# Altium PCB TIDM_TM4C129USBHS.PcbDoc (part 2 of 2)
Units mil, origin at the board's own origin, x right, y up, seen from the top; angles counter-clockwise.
Board outline 3900 x 3450 mil, 4 copper layers (Component Side, Ground Plane, Power Plane, Solder Side), stack 59.6 mil thick; 136 components, 129 nets, 585 pads, 295 vias.
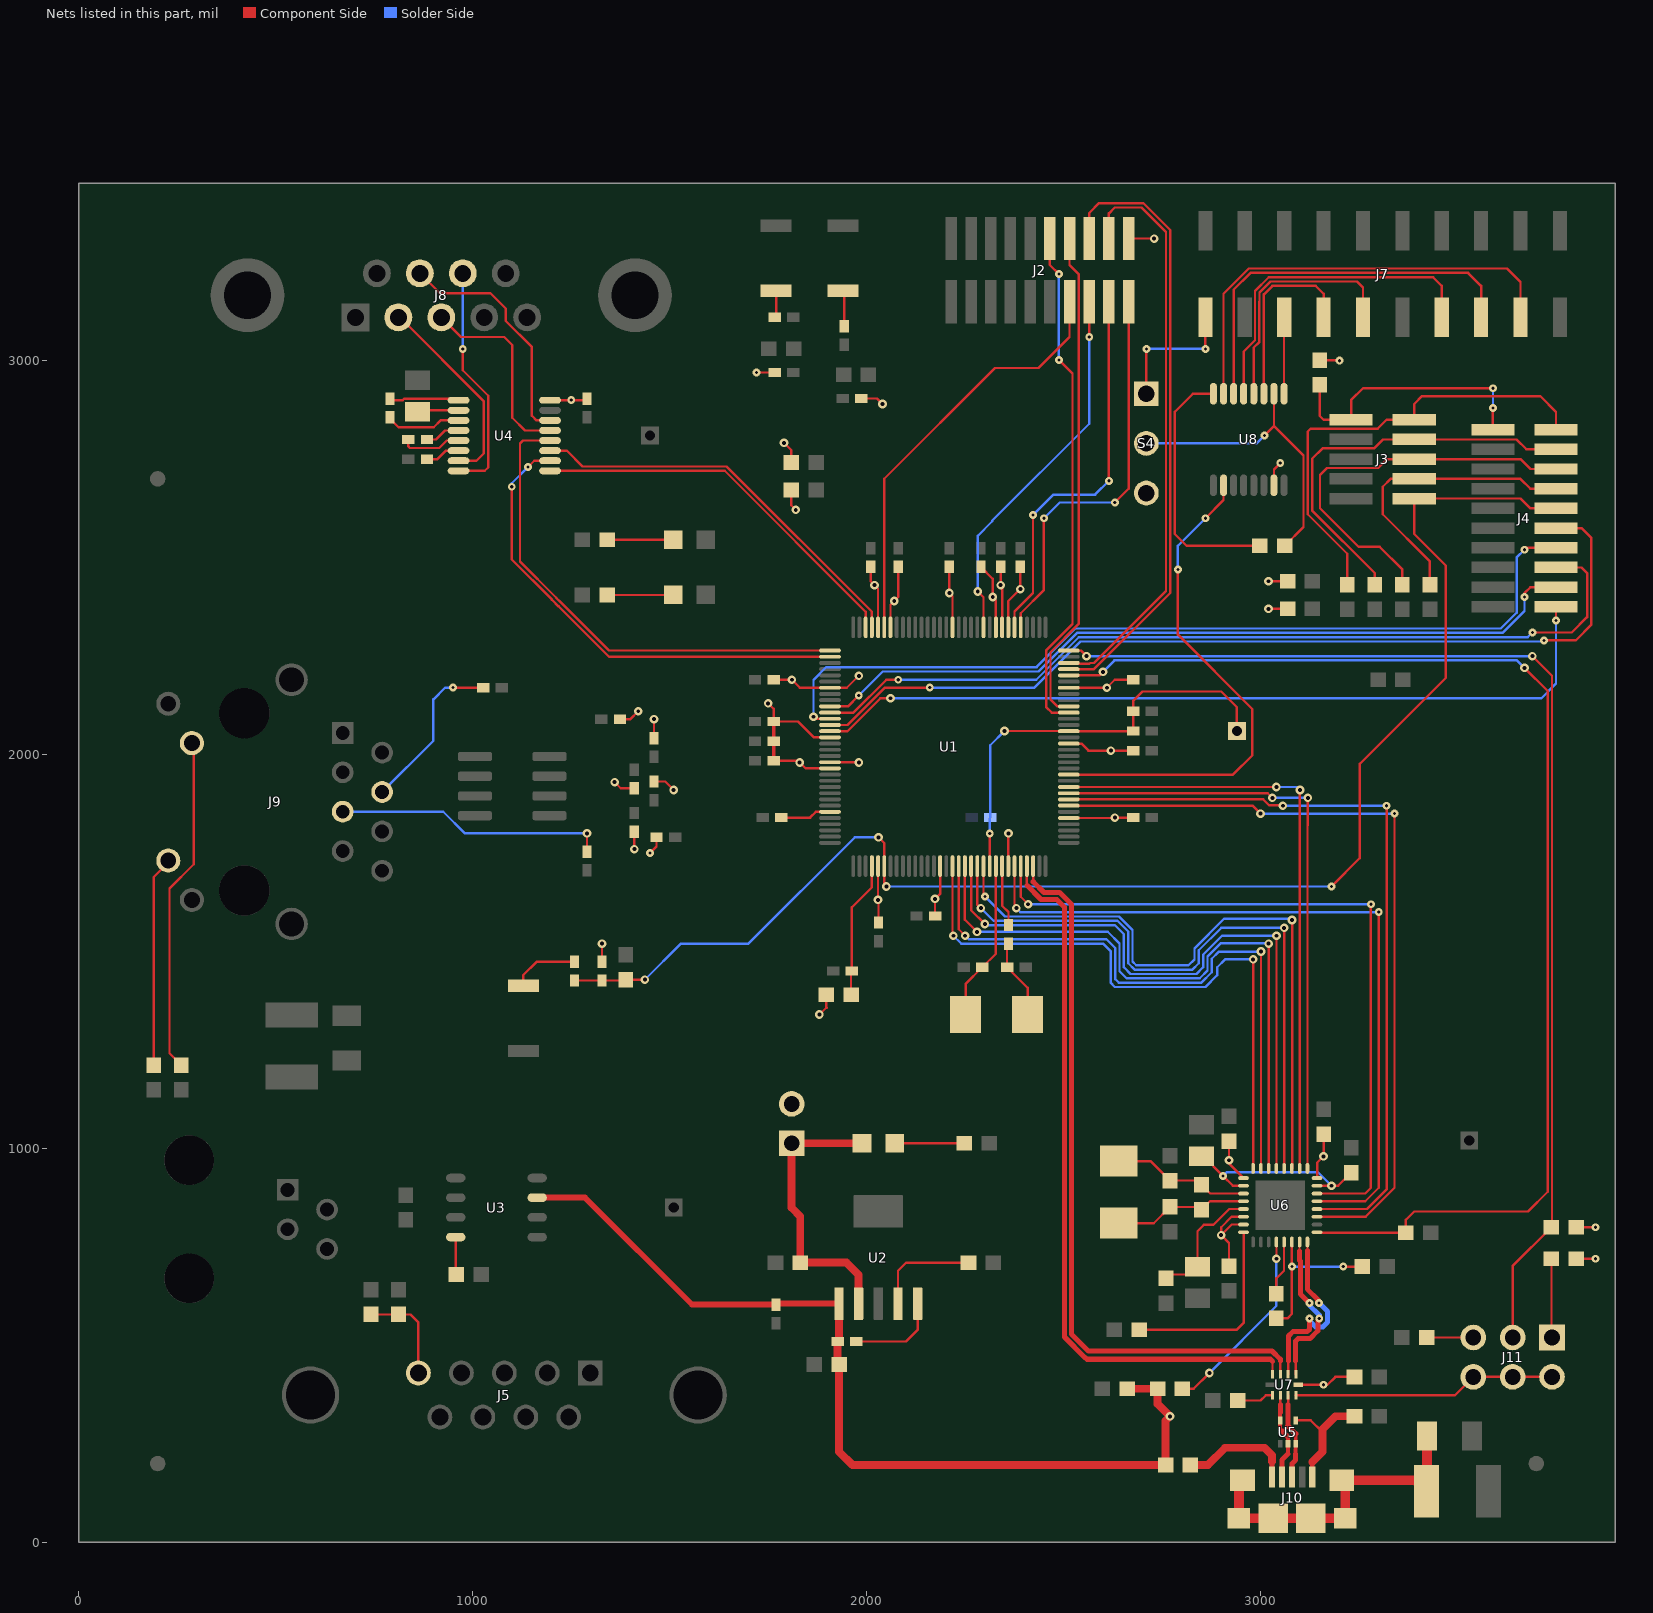
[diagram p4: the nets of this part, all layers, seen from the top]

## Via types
v1: diameter 22, hole 10, Component Side to Solder Side, 140 vias
v2: diameter 20, hole 8, Component Side to Solder Side, 139 vias
v3: diameter 19.68, hole 8, Component Side to Solder Side, 16 vias

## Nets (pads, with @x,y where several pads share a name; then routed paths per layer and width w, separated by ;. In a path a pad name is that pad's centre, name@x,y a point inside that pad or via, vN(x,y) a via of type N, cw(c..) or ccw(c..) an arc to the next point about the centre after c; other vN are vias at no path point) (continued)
MCU_GPIO5: U1.108 U8.10 | length 1298.3
  Component Side w6: U1.108@2513.15,1949.13 2930.19,1949.13 2979,1997.94 2979,2115.44 2790,2304.44 v2(2790,2470) ; v2(2860,2600) 2906.02,2646.02 U8.10@2906.02,2683.86
  Solder Side w6: v2(2790,2470) 2790,2530 v2(2860,2600)
NetC1_1: C1.1 R1.2 U1.68 | length 348.3
  Component Side w6: R1.2@1960.28,1390.5 1960.28,1448.37 C1.1@1962.4,1450.5 1962.4,1612.4 2013.15,1663.15 U1.68@2013.15,1716.85
NetC17_1: C17.1 C18.1 C19.1 TP1.1 U1.87 U1.115 | length 1112.4
  Component Side w4.8: C18.1@2662.99,2059.37 2662.99,2060 C18.1@2676.38,2060
  Component Side w6: U1.87@2312.36,1716.85 v2(2312.36,1800) ; v1(2350,2060) 2512.52,2060 U1.115@2513.15,2059.37 C18.1@2662.99,2059.37 ; C18.1@2676.38,2060 C17.1@2676.38,2110 2676.38,2136.38 2700,2160 2900,2160 2940,2120 TP1.1@2940,2060
  Solder Side w6: v2(2312.36,1800) 2312.36,1838.74 C19.1@2313.62,1840 2313.62,2023.62 v1(2350,2060)
NetC20_1: C20.1 U1.88 Y1.2 | length 408.7
  Component Side w6: Y1.2@2251.26,1340 2251.26,1417.64 C20.1@2293.62,1460 2328.11,1494.49 U1.88@2328.11,1716.85
NetC21_1: C21.1 R2.2 Y1.1 | length 203.2
  Component Side w6: R2.2@2360,1520 2356.38,1516.38 C21.1@2356.38,1460 2360,1456.38 2408.74,1407.64 Y1.1@2408.74,1340
NetC24_1: C24.1 U2.4 | length 271.8
  Component Side w6: U2.4@2080,605.44 U2.4@2079.49,605.95 2079.49,689.49 2100,710 C24.1@2258.5,710
NetC25_1: C25.1 D1.1 J1.1 U2.2 | length 725
  Component Side w20: U2.2@1979.49,605.95 1979.49,679.49 1948.98,710 C25.1@1831.5,710 1831.5,827.49 1809.49,849.49 J1.1@1809.49,1013.08 D1.1@1988.15,1013.08
NetC27_1: C27.1 J5.5 R20.2 | length 257.1
  Component Side w6: C27.1@741.46,578.5 R20.2@811.46,578.5 841.5,578.5 861.89,558.11 J5.5@861.89,429.92
NetC30_1: C30.1 U4.1 | length 180.4
  Component Side w6: C30.1@790,2903.62 794.06,2899.57 821.75,2899.57 825.19,2903 963.86,2903 U4.1@963.86,2899.57
NetC30_2: C30.2 U4.3 | length 196.3
  Component Side w6: C30.2@790,2856.38 790,2852.44 811.65,2830.79 900.79,2830.79 918.39,2848.39 U4.3@963.86,2848.39 U4.3@965.47,2850
NetC31_1: C31.1 U4.4 | length 90.8
  Component Side w6: C31.1@883.62,2800 906.46,2800 929.25,2822.8 U4.4@963.86,2822.8 U4.4@963.03,2823.62
NetC31_2: C31.2 U4.5 | length 154.8
  Component Side w6: C31.2@836.38,2800 836.38,2781.97 840,2778.35 914.8,2778.35 933.66,2797.2 U4.5@963.86,2797.2
NetC32_2: C32.2 U4.2 | length 105.5
  Component Side w6: C32.2@860,2870 863.98,2873.98 U4.2@963.86,2873.98
NetC33_1: C33.1 U4.6 | length 89.2
  Component Side w6: C33.1@883.62,2750 910,2750 931.61,2771.61 U4.6@963.86,2771.61
NetC48_1: C48.1 R36.2 U6.28 Y2.1 | length 345.6
  Component Side w6: Y2.1@2640,810.26 2728.76,810.26 C48.1@2770,851.5 2843.35,851.5 R36.2@2850.2,844.65 2871.54,865.98 U6.28@2956.89,865.98
NetC49_1: C49.1 R36.1 U6.27 Y2.2 | length 350.9
  Component Side w6: Y2.2@2640,967.74 2720.76,967.74 C49.1@2770,918.5 2839.33,918.5 R36.1@2850.2,907.64 2872.17,885.67 U6.27@2956.89,885.67
NetD1_2: D1.2 R7.1 | length 177.2
  Component Side w6: D1.2@2070.83,1013.08 R7.1@2248,1013.08
NetD2_2: D2.2 R21.1 | length 167.2
  Component Side w6: R21.1@1341.32,2545.28 D2.2@1508.49,2545.28
NetD3_2: D3.2 R22.1 | length 167.2
  Component Side w6: R22.1@1341.32,2405.28 D3.2@1508.49,2405.28
NetJ7_1: J7.1 S4.1 | length 344
  Component Side w6: S4.1@2710,2916 v2(2710,3030) ; v2(2860,3030) J7.1@2860,3110
  Solder Side w6: v2(2710,3030) v2(2860,3030)
NetJ7_5: J7.5 U8.1 | length 194
  Component Side w6: U8.1@3059.57,2916.14 3059.57,3109.57 J7.5@3060,3110
NetJ7_7: J7.7 U8.3 | length 481.1
  Component Side w6: U8.3@3008.39,2916.14 3008.39,3168.39 3030,3190 3140,3190 3160,3170 J7.7@3160,3110
NetJ7_9: J7.9 U8.4 | length 619
  Component Side w6: U8.4@2982.8,2916.14 2982.8,3033.24 2997,3047.44 2997,3150 2997.39,3150.39 2997.39,3172.94 3025.44,3201 3244.5,3201 3260,3185.5 J7.9@3260,3110
NetJ7_13: J7.13 U8.5 | length 850.5
  Component Side w6: U8.5@2957.2,2916.14 2957.2,3023.2 2986,3052 2986,3177.11 3020.89,3212 3438,3212 3460,3190 J7.13@3460,3110
NetJ7_15: J7.15 U8.6 | length 1003.7
  Component Side w6: U8.6@2931.61,2916.14 2931.61,3180 2974.61,3223 3527,3223 3560,3190 J7.15@3560,3110
NetJ7_17: J7.17 U8.7 | length 1138.4
  Component Side w6: U8.7@2906.02,2916.14 2906.02,3169.97 2970.06,3234 3626,3234 3660,3200 J7.17@3660,3110
NetJ8_2: J8.2 U4.7 | length 509.6
  Component Side w6: J8.2@810.94,3110.08 814.92,3110.08 1028.22,2896.78 1028.22,2765 1009.24,2746.02 U4.7@963.86,2746.02
NetJ8_3: J8.3 U4.13 | length 503.5
  Component Side w6: J8.3@920,3110.08 970.08,3060 1080,3060 1100,3040 1100,2855 1132.2,2822.8 U4.13@1196.14,2822.8
NetJ8_7: J8.7 U4.14 | length 606.1
  Component Side w6: J8.7@865.47,3221.89 916.36,3171 1045.11,3171 1083.49,3132.63 1083.49,3101.07 1150,3034.56 1150,2860 1161.61,2848.39 U4.14@1196.14,2848.39
NetJ8_8: J8.8 U4.8 | length 598.5
  Component Side w6: U4.8@963.86,2720.43 1030.43,2720.43 1039.22,2729.22 1039.22,2911.02 974.53,2975.71 v2(974.53,3030)
  Solder Side w6: v2(974.53,3030) J8.8@974.53,3221.89
NetJ9_10: J9.10 R32.1 | length 855.5
  Component Side w6: R32.1@260,1211.5 230,1241.5 230,1660 291.73,1721.73 J9.10@291.73,2029.02
NetJ9_11: J9.11 R33.1 | length 536.8
  Component Side w6: R33.1@190,1211.5 190,1689.09 J9.11@231.89,1730.98
NetJ11_1: J11.1 R41.1 | length 200.6
  Component Side w6: R41.1@3738.5,720 3738.5,521.5 J11.1@3740,520
NetJ11_2: J11.2 J11.4 J11.6 U7.9 | length 669.8
  Component Side w6: U7.9@3089.53,373.43 3493.43,373.43 J11.6@3540,420 J11.4@3640,420 J11.2@3740,420
NetJ11_5: J11.5 R42.1 | length 120.6
  Component Side w6: R42.1@3421.5,520 J11.5@3540,520 J11.5@3541.5,521.5
NetR2_1: R2.1 U1.89 | length 156.3
  Component Side w6: U1.89@2343.86,1716.85 2343.86,1616.14 2360,1600 R2.1@2360,1567.24
NetR3_2: R3.2 U1.59 | length 129.3
  Component Side w6: R3.2@1783.62,1840 1856.35,1840 1871,1854.65 U1.59@1906.85,1854.65
NetR4_2: R4.2 S1.2 | length 171.2
  Component Side w6: S1.2@1128.19,1412.68 1128.19,1440 1161.81,1473.62 R4.2@1258.19,1473.62
NetR6_2: R6.2 U2.5 | length 235
  Component Side w6: R6.2@1973.62,510 2100,510 2130,540 2129.49,540.51 U2.5@2129.49,605.95
NetR18_2: R18.2 U3.8 | length 95.8
  Component Side w6: U3.8@956.65,775 956.65,681.85 R18.2@958.5,680
NetR23_2: R23.2 S2.2 | length 83.7
  Component Side w6: R23.2@1943,3087.61 S2.2@1943,3171.31
NetR25_2: R25.2 S3.2 | length 68.8
  Component Side w6: R25.2@1766.38,3110 1770,3113.62 S3.2@1770,3177.32
NetR27_1: R27.1 U8.8 | length 656.5
  Component Side w6: U8.8@2880.43,2916.14 2828.14,2916.14 2782,2870 2782,2560 2812,2530 R27.1@2998.5,2530
NetR27_2: R27.2 S4.2 U8.2 | length 779.1
  Component Side w6: v2(3010,2810) 3033.98,2833.98 ; U8.2@3033.98,2916.14 3033.98,2833.98 ; R27.2@3061.5,2530 3109,2577.5 3109,2758.95 3033.98,2833.98
  Solder Side w6: S4.2@2710,2790 2990,2790 v2(3010,2810)
NetR35_1: R35.1 U6.5 | length 139.6
  Component Side w6: R35.1@3040,631.5 3040,670 3059.5,689.5 3059.5,762.29 U6.5@3060.04,762.83
NetR37_1: R37.1 U6.4 | length 488.5
  Component Side w6: R37.1@2801.5,390 2830,390 v1(2870,430) ; v1(3040,720) 3040.36,720.36 U6.4@3040.36,762.83
  Solder Side w6: v1(2870,430) 3040,600 v1(3040,720)
NetR38_2: R38.2 U6.32 | length 502.7
  Component Side w6: R38.2@2691.5,540 2940,540 2956.89,556.89 U6.32@2956.89,787.24
NetR40_2: R40.2 U7.6 | length 95.2
  Component Side w6: R40.2@2941.5,360 3000,360 3013.43,373.43 U7.6@3030.47,373.43 U7.6@3030,372.95
RST_N: C22.1 J3.10 J4.10 R4.1 R5.1 U1.70 | length 3694.3
  Component Side w6: R4.1@1258.19,1426.38 R5.1@1328.19,1426.38 1386.06,1426.38 C22.1@1388.19,1428.5 v1(1436.69,1428.5) ; v1(2030,1790) 2044.65,1775.35 U1.70@2044.65,1716.85 2044.65,1670.35 v1(2050,1665) ; v2(3180,1665) 3252,1737 3252,1976.44 3470,2194.44 3470,2480 3390.12,2559.88 J3.10@3390.12,2650 3660,2650 3685,2625 J4.10@3750.12,2625
  Solder Side w6: v1(1436.69,1428.5) 1528.19,1520 1700,1520 1970,1790 v1(2030,1790) ; v1(2050,1665) v2(3180,1665)
SSI3CLK: J2.2 U1.5 | length 1022.2
  Component Side w6: U1.5@2391.1,2323.15 2391.1,2359 2450,2417.9 v2(2450,2600) ; v2(2630,2640) 2665,2675 J2.2@2665,3149.88
  Solder Side w6: v2(2450,2600) 2490,2640 v2(2630,2640)
SSI3FSS: J2.4 U1.6 | length 988.1
  Component Side w6: U1.6@2375.35,2323.15 2375.35,2363 2422.35,2410 v2(2422.35,2608.35) ; v2(2615,2695) J2.4@2615,3149.88
  Solder Side w6: v2(2422.35,2608.35) 2474,2660 2580,2660 v2(2615,2695)
SSI3XDAT0: J2.6 U1.11 | length 962.6
  Component Side w6: v1(2282,2414) 2296.61,2399.39 U1.11@2296.61,2323.15 ; v2(2565,3060) J2.6@2565,3149.88 J2.6@2565,3162.5
  Solder Side w6: v1(2282,2414) 2282,2555.13 2319,2592.13 2319,2594 2565,2840 v2(2565,3060)
SSI3XDAT1: J2.8 U1.27 | length 1086.3
  Component Side w6: U1.27@2044.65,2323.15 2044.65,2700.17 2325.97,2981.5 2436.5,2981.5 2515,3060 J2.8@2515,3149.88
SSI3XDAT2: J2.9 U1.118 | length 1304.2
  Component Side w6: J2.9@2465,3310.12 2465,3243 v2(2488,3220) ; v2(2488,3002) 2522.59,2967.41 2522.59,2331.55 2455.59,2264.56 2455.59,2121.02 2470,2106.61 U1.118@2513.15,2106.61
  Solder Side w6: v2(2488,3002) v2(2488,3220)
SSI3XDAT3: J2.7 U1.119 | length 1263.1
  Component Side w6: U1.119@2513.15,2122.36 2484.23,2122.36 2466.59,2140 2466.59,2260 2538,2331.41 2538,3220 2515,3243 J2.7@2515,3310.12
TCK_INT: J3.4 J4.4 R12.1 | length 1035.1
  Component Side w6: R12.1@3290,2431.49 3290,2460.75 3131,2619.75 3131,2751 3157.43,2777.43 3288.11,2777.43 3310.68,2800 J3.4@3390.12,2800 3650,2800 3675,2775 J4.4@3750.12,2775
TDI_INT: J3.8 J4.8 R14.1 | length 757
  Component Side w6: R14.1@3430,2431.49 3430,2490 3310,2610 3310,2680 3330,2700 J3.8@3390.12,2700 3660,2700 3685,2675 J4.8@3750.12,2675
TDO_INT: J3.6 J4.6 R13.1 | length 1022.6
  Component Side w6: R13.1@3360,2431.49 3360,2470 3302.22,2527.78 3248.55,2527.78 3151,2625.33 3151,2710 3168.43,2727.43 3298.43,2727.43 3321,2750 J3.6@3390.12,2750 3660,2750 3685,2725 J4.6@3750.12,2725
TMS_INT: J3.2 J4.2 R11.1 | length 1182.3
  Component Side w6: R11.1@3220,2431.49 3220,2510 3120,2610 3120,2820 3127.43,2827.43 3297.43,2827.43 3320,2850 3390,2850 J3.2@3390.12,2850 3390.12,2890 3410.12,2910 3710.12,2910 3750.12,2870 J4.2@3750.12,2825
TRCLK: J4.12 U1.45 | length 2360
  Component Side w6: U1.45@1906.85,2075.12 1951.26,2075.12 2046.14,2170 v2(2160,2170) ; v2(3720,2290) 3800,2290 3840,2330 3840,2550 3815,2575 J4.12@3750.12,2575
  Solder Side w6: v2(2160,2170) 2426.06,2170 2543.06,2287 3717,2287 v2(3720,2290) ; 2525.82,2268.23 2526.59,2269
TRD0: J4.14 U1.44 | length 2243.6
  Component Side w6: v1(1865,2096) 1870.13,2090.87 U1.44@1906.85,2090.87 ; v2(3670,2520) 3675,2525 J4.14@3750.12,2525
  Solder Side w6: v1(1865,2096) 1865,2189.5 1897.5,2222 2431.39,2222 2529.39,2320 3610,2320 3650,2360 3650,2500 v2(3670,2520)
TRD1: J4.16 U1.43 | length 2219.2
  Component Side w6: U1.43@1906.85,2106.61 1966.61,2106.61 2050,2190 v2(2080,2190) ; v2(3690,2310) 3790,2310 3829,2349 3829,2461 3815,2475 J4.16@3750.12,2475
  Solder Side w6: v2(2080,2190) 2430.5,2190 2538.5,2298 3678,2298 v2(3690,2310)
TRD2: J4.18 U1.42 | length 1995.3
  Component Side w6: U1.42@1906.85,2122.36 1952.36,2122.36 v2(1980,2150) ; v2(3670,2400) 3670,2410 3685,2425 J4.18@3750.12,2425
  Solder Side w6: v2(1980,2150) 2041,2211 2435.94,2211 2533.94,2309 3614.56,2309 3670,2364.44 v2(3670,2400)
TRD3: J4.20 U1.46 | length 2088.2
  Component Side w6: U1.46@1906.85,2059.37 1951.07,2059.37 2034.7,2143 v1(2060.5,2143) ; v2(3750.12,2340.12) J4.20@3750.12,2375
  Solder Side w6: v1(2060.5,2143) 3713,2143 3750.12,2180.12 v2(3750.12,2340.12)
U0CTS: U1.30 U4.9 | length 988.9
  Component Side w6: U4.9@1196.14,2720.43 1639.57,2720.43 1997.4,2362.6 U1.30@1997.4,2323.15
U0RTS: U1.29 U4.11 | length 1025.8
  Component Side w6: U4.11@1196.14,2771.61 1238.39,2771.61 1278.57,2731.43 1644.12,2731.43 2013.15,2362.41 U1.29@2013.15,2323.15
U0RX: U1.33 U4.12 | length 1264.9
  Component Side w6: U4.12@1196.14,2797.2 1127.2,2797.2 1120,2790 1120,2490 1211.83,2398.17 1211.83,2397.83 1222.37,2387.28 1222.72,2387.28 1345.91,2264.09 U1.33@1906.85,2264.09 U1.33@1912,2264.09
U0TX: U1.34 U4.10 | length 1224.7
  Component Side w6: v2(1099,2680) 1099,2495.44 1200.83,2393.61 1200.83,2393.27 1217.82,2376.28 1218.16,2376.28 1346.1,2248.35 U1.34@1906.85,2248.35 ; v2(1140,2730) 1156.02,2746.02 U4.10@1196.14,2746.02
  Solder Side w6: v2(1099,2680) 1099,2689 v2(1140,2730)
U2RX: J2.5 U1.125 | length 1568.3
  Component Side w6: U1.125@2513.15,2216.85 2576.85,2216.85 2771,2411 2771,3331.28 2702.28,3400 2590,3400 2565,3375 J2.5@2565,3310.12
U2TX: J2.3 U1.126 | length 1476
  Component Side w6: U1.126@2513.15,2232.6 2514.75,2231 2565.87,2231 2567.47,2232.6 2577.04,2232.6 2760,2415.56 2760,3326.72 2697.72,3389 2630,3389 2615,3374 J2.3@2615,3310.12
U_GND: FB2.1 J10.5 U5.4 | length 307
  Component Side w6: U5.4@3089.21,309.53 3127.46,309.53 3156.99,280
  Component Side w12: J10.5@3131.18,166.34 3131.18,204.19
  Component Side w20: 3131.18,204.19 3156.99,230 3156.99,260 ; 3156.67,260.31 3156.99,260 ; FB2.1@3238.5,320 3190,320 3156.99,286.99 3156.99,280 3156.99,260
U_SHIELD: C52.1 J10.6 J10.7 J10.8 J10.9 J10.10 J10.11 R44.2 | length 827.8
  Component Side w25: J10.6@2954.02,158.02 2945.16,149.16 J10.8@2945.16,61.02 J10.10@3127.24,61.02 J10.11@3214.84,61.02 3214.84,148.62 J10.7@3205.98,157.48 3393.78,157.48 C52.1@3421.26,130 3422.91,131.65 R44.2@3422.91,260
U_VBUS: FB1.2 J10.1 | length 287.9
  Component Side w12: J10.1@3028.82,166.34 3028.82,205
  Component Side w20: FB1.2@2821.69,196.14 2866.14,196.14 2910,240 3010,240 3028.82,221.18 3028.82,205
ULPI_CLK: U1.92 U6.14 | length 1837.1
  Component Side w6: U1.92@2391.1,1716.85 2391.1,1638.9 v1(2410,1620) ; U6.14@3143.51,885.67 3265.67,885.67 3280,900 v2(3280,1620)
  Solder Side w6: v1(2410,1620) v2(3280,1620)
ULPI_D0: U1.81 U6.24 | length 1611
  Component Side w6: U1.81@2217.87,1716.85 2217.87,1542.13 v1(2220,1540) ; U6.24@2981.3,949.45 v1(2981.3,1480)
  Solder Side w6: v1(2220,1540) 2240,1520 2600,1520 2620,1500 2620,1420 2630,1410 2860,1410 2890,1440 2890,1460 2910,1480 v1(2981.3,1480)
ULPI_D1: U1.82 U6.23 | length 1633.7
  Component Side w6: U1.82@2233.62,1716.85 2233.62,1556.38 v1(2250,1540) ; U6.23@3000.99,949.45 v1(3000.99,1500)
  Solder Side w6: v1(2250,1540) 2259,1531 2609,1531 2631,1509 2631,1430 2640,1421 2850,1421 2876.22,1447.22 2876.22,1481.78 2893.44,1499 2999.99,1499 v1(3000.99,1500)
ULPI_D2: U1.83 U6.22 | length 1638.3
  Component Side w6: U1.83@2249.37,1716.85 2249.37,1580.63 v1(2280,1550) ; U6.22@3020.67,949.45 v1(3020.67,1520)
  Solder Side w6: v1(2280,1550) 2612,1550 2642,1520 2642,1450 2660,1432 2845.44,1432 2865.22,1451.78 2865.22,1487.22 2898.56,1520.56 3020.11,1520.56 v1(3020.67,1520)
ULPI_D3: U1.84 U6.21 | length 1652.8
  Component Side w6: U1.84@2265.12,1716.85 2265.12,1604.88 v1(2300,1570) ; U6.21@3040.36,949.45 v1(3040.36,1540)
  Solder Side w6: v1(2300,1570) 2303,1567 2630,1567 2653,1544 2653,1460 2670,1443 2837.22,1443 2854.22,1460 2854.22,1491.78 2902.44,1540 v1(3040.36,1540)
ULPI_D4: U1.85 U6.20 | length 1666.3
  Component Side w6: U1.85@2280.87,1716.85 2280.87,1619.13 v1(2290,1610) ; U6.20@3060.04,949.45 v1(3060.04,1560)
  Solder Side w6: v1(2290,1610) 2322,1578 2636.44,1578 2664,1550.44 2664,1470 2680,1454 2827.22,1454 2843.22,1470 2843.22,1503.22 2900,1560 v1(3060.04,1560)
ULPI_D5: U1.86 U6.19 | length 1674.9
  Component Side w6: U1.86@2296.61,1716.85 2296.61,1643.39 v2(2300,1640) ; U6.19@3079.73,949.45 3080,949.72 v1(3080,1580)
  Solder Side w6: v2(2300,1640) 2351,1589 2641,1589 2675,1555 2675,1474.56 2684.56,1465 2817.22,1465 2832.22,1480 2832.22,1507.78 2907.44,1583 3077,1583 v1(3080,1580)
ULPI_D6: U1.106 U6.18 | length 1550.8
  Component Side w6: U1.106@2513.15,1917.64 v1(3040,1917.64) ; U6.18@3099.41,949.45 3099.41,1909.41 v1(3100,1910)
  Solder Side w6: v1(3040,1917.64) 3092.36,1917.64 v1(3100,1910)
ULPI_D7: U1.105 U6.17 | length 1552.7
  Component Side w6: U1.105@2513.15,1901.89 3018.11,1901.89 v1(3030,1890) ; U6.17@3119.1,949.45 3119.1,1820 3120,1820.9 v1(3120,1890)
  Solder Side w6: v1(3030,1890) v1(3120,1890)
ULPI_DIR: U1.104 U6.12 | length 1984.8
  Component Side w6: U1.104@2513.15,1886.14 3006.99,1886.14 3022.13,1871 3055.46,1871 v1(3056.46,1870) ; U6.12@3143.31,846.16 3270,846.16 3320,896.16 v2(3320,1870)
  Solder Side w6: v1(3056.46,1870) v2(3320,1870)
ULPI_NXT: U1.103 U6.11 | length 2012.2
  Component Side w6: U1.103@2513.15,1870.39 2979.61,1870.39 v1(3000,1850) ; U6.11@3143.51,826.61 3266.61,826.61 3340,900 v2(3340,1850)
  Solder Side w6: v1(3000,1850) v2(3340,1850)
ULPI_STP: U1.91 U6.13 | length 1903.5
  Component Side w6: U1.91@2375.35,1716.85 2375.35,1614.65 v1(2380,1610) ; U6.13@3143.51,865.98 3265.98,865.98 3300,900 v2(3300,1600)
  Solder Side w6: v1(2380,1610) 2390,1600 v2(3300,1600)
USBCONN_N: J10.2 U5.2 U5.5 U7.7 | length 244.9
  Component Side w6: 3050.16,350 U7.7@3050.16,373.43 3050.16,350
  Component Side w9.45: U5.2@3069.53,250.47 3069.53,267.65
  Component Side w10: 3049.84,329.61 U5.5@3049.84,309.53 3049.84,287.33 3055.75,281.43 ; 3069.53,224.56 U5.2@3069.53,250.47
  Component Side w12.8: 3050.16,329.61 3050.16,350 ; J10.2@3054.41,166.34 3054.41,209.44 3069.53,224.56
  Component Side w14: 3055.75,281.43 3069.53,267.65
USBCONN_P: J10.3 U5.3 U7.8 | length 218.7
  Component Side w6: 3069.84,350.31 U7.8@3069.84,373.43
  Component Side w9.45: 3089.21,235.63 U5.3@3089.21,250.47 3089.21,275.52
  Component Side w10: 3089.21,224.56 3089.21,235.63
  Component Side w12.8: 3069.53,295.2 3069.53,350 ; J10.3@3080,166.34 3080,199.73 3089.21,208.94 3089.21,224.56
  Component Side w14: 3069.53,295.2 3089.21,275.52
USBD_N: U1.93 U7.4 | length 1845.3
  Component Side w6: 2406.85,1667.98 U1.93@2406.85,1716.85 ; U7.4@3030.47,426.57 3030.47,459.53
  Component Side w12.8: 2406.85,1667.98 2442.63,1632.2 2482.63,1632.2 2502.37,1612.45 2502.37,521.1 2555.27,468.2 2556.54,468.2 2559.96,464.79 3025.21,464.79 3030.47,459.53
USBD_P: U1.94 U7.3 | length 1846.9
  Component Side w6: U1.94@2422.6,1716.85 2422.85,1716.6 2422.85,1677.15 ; U7.3@3050.16,426.57 3050.16,460
  Component Side w12.8: 2422.85,1677.15 2450,1650 2490,1650 2520.17,1619.83 2520.17,528.47 2562.64,486 3029.17,486 3050.16,465.02 3050.16,460
USBHS_N: U6.8 U7.2 | length 473.7
  Component Side w5: 3118.9,741.1 U6.8@3118.9,762.69
  Component Side w6: U7.2@3069.84,426.57 3069.84,459.84 3070.79,460.79
  Component Side w12.8: 3070.79,460.79 3070.79,523.79 3081.79,534.79 3118.21,534.79 3124,540.59 v2(3124,568) ; 3118.73,700.17 3118.73,642.76 3145.21,616.28 3145.21,611.01 v2(3148.81,607.41) ; 3118.9,700.17 3118.9,741.1
  Solder Side w12.8: v2(3124,568) 3124,562.74 3140.14,546.6 3157.86,546.6 3170.4,559.14 3170.4,585.83 v2(3148.81,607.41)
USBHS_P: U6.7 U7.1 | length 426.7
  Component Side w5: 3099.21,739.21 U6.7@3099.21,762.69
  Component Side w6: 3088.59,460.47 3089.53,459.53 U7.1@3089.53,426.57 3089.53,453.21
  Component Side w12.8: 3088.59,460.47 3088.59,510.58 3095,516.99 3125.58,516.99 3145.4,536.81 3145.4,564.4 v2(3149,568) ; 3099.21,739.21 3099.21,715.61 3100.93,713.9 3100.93,630.3 v2(3123.81,607.41)
  Solder Side w12.8: v2(3123.81,607.41) 3123.81,602.15 3149,576.96 v2(3149,568)
USBMUX_SEL: J11.3 R43.1 U1.128 | length 2974.8
  Component Side w6: U1.128@2513.15,2264.09 2543.91,2264.09 v1(2558,2250) ; J11.3@3640,520 3640,701.5 R43.1@3738.5,800 3740,801.5 3740,2200 v1(3690,2250)
  Solder Side w6: v1(2558,2250) v1(3690,2250)
USBPHY_RST: R39.2 U1.124 U6.9 | length 3182.9
  Component Side w6: U1.124@2513.15,2201.1 2591.1,2201.1 v1(2600,2210) ; U6.9@3143.51,787.24 3144.61,786.14 R39.2@3368.7,786.14 3368.7,818.7 3390,840 3679,840 3729,890 3729,2161 v1(3670,2220)
  Solder Side w6: v1(2600,2210) 2629,2239 3651,2239 v1(3670,2220)
VCC_1P8: C44.1 C45.1 U6.15 U6.26 | length 531.7
  Component Side w6: C44.1@2850,980 2854.84,980 v2(2904.84,930) 2929.63,905.21 U6.26@2956.69,905.21 ; U6.26@2956.69,905.35 U6.26@2956.89,905.35 ; U6.15@3143.51,905.35 v1(3180,905.35) 3196.85,905.35 C45.1@3230,938.5
  Solder Side w6: v2(2904.84,930) 2914.84,940 3145.35,940 v1(3180,905.35)
VCC_1P8A: C46.1 C47.1 U6.29 | length 320.5
  Component Side w6: C47.1@2760.2,670 2770.2,680 2816.71,680 2840,703.29 2840,790 2856.14,806.14 2880.2,806.14 2920.36,846.3 U6.29@2956.89,846.3
VCC_3P3: C2.1 C3.1 C4.1 C5.1 C6.1 C7.1 C8.1 C9.1 C10.1 C11.1 C12.1 C13.1 C14.1 C15.1 C16.1 C34.1 C35.1 C36.1 C37.1 C38.1 C40.1 C41.1 C42.1 C43.1 C51.2 J1.2 J2.1 J9.4 J9.5 R1.1 R5.2 R8.2 R9.2 R10.1 R15.2 R16.2 R24.2 R26.2 R28.2 R29.2 R30.2 R31.2 R35.2 R41.2 R43.2 S4.3 U1.7 U1.8 U1.9 U1.16 U1.26 U1.28 U1.39 U1.47 U1.51 U1.52 U1.69 U1.79 U1.90 U1.101 U1.113 U1.122 U4.16 U6.6 U6.16 U6.25 U6.30 U6.31 U7.10 U8.15 | length 5961
  Component Side w6: v2(950,2170) C37.1@1026.38,2170 ; U4.16@1196.14,2899.57 1249.57,2899.57 v2(1250,2900) 1286.38,2900 C34.1@1290,2903.62 ; C38.1@1290,1753.62 v1(1290,1800) ; R5.2@1328.19,1473.62 v1(1328.19,1520) ; v1(1360,1930) 1375.62,1914.38 R30.2@1410,1914.38 ; C36.1@1373.62,2090 1400,2090 v1(1420,2110) ; v1(1410,1760) R28.2@1410,1804.38 ; v2(1450,1750) 1466.38,1766.38 C35.1@1466.38,1790 ; R29.2@1460,1931.62 1488.38,1931.62 v1(1510,1910) ; R31.2@1460,2041.62 v1(1460,2090) ; v2(1720,2970) R26.2@1766.38,2970 ; v1(1750,2130) 1763.62,2116.38 C6.1@1763.62,2084 ; C16.1@1763.62,2034 C16.1@1763,2034 ; C9.1@1763.62,2190 v1(1810,2190) 1830.39,2169.61 U1.39@1906.85,2169.61 1949.61,2169.61 v1(1980,2200) ; v1(1790,2791.46) 1808.5,2772.95 R9.2@1808.5,2741.46 ; R8.2@1808.5,2671.46 1808.5,2632.95 v1(1820,2621.46) ; v1(1880,1340) 1897.28,1357.28 1897.28,1358 ; R1.1@1897.28,1390.5 1897.28,1358 ; 1898.28,1357 1897.28,1358 ; U1.52@1906.85,1964.88 1845.12,1964.88 v1(1830,1980) 1826,1984 C8.1@1766,1984 ; U1.51@1906.85,1980.63 1979.37,1980.63 v1(1980,1980) ; U1.47@1906.85,2043.62 1866.38,2043.62 1826,2084 C6.1@1766,2084 ; R24.2@1986.63,2903.99 2026.01,2903.99 v1(2040,2890) ; C7.1@2010,2476.38 2010,2440 v1(2020,2430) 2028.9,2421.1 U1.28@2028.9,2323.15 ; U1.69@2028.9,1716.85 v1(2028.9,1631.1) 2030,1630 C12.1@2030,1573.62 ; U1.26@2060.39,2323.15 2060.39,2380.39 v1(2070,2390) 2080,2400 C4.1@2080,2476.38 ; C13.1@2173.62,1590 v1(2173.62,1633.62) 2186.38,1646.38 U1.79@2186.38,1716.85 ; C5.1@2210,2476.38 v1(2210,2410) 2217.87,2402.13 U1.16@2217.87,2323.15 ; C2.1@2290,2476.38 2290,2476 2320,2446 v1(2320,2400) 2328.11,2391.89 U1.9@2328.11,2323.15 ; C3.1@2340,2476.38 v1(2340,2430) 2343.86,2426.14 U1.8@2343.86,2323.15 ; U1.90@2359.61,1716.85 2359.61,1799.61 v1(2360,1800) ; U1.7@2359.61,2323.15 2359.61,2389.61 v1(2390,2420) C15.1@2390,2476.38 ; U1.101@2513.15,1838.9 2628.9,1838.9 v1(2630,1840) C14.1@2676.38,1840 ; U1.113@2513.15,2027.87 2545,2027.87 2562.87,2010 v1(2620,2010) C11.1@2676.38,2010 ; U1.122@2513.15,2169.61 v1(2609.61,2169.61) 2630,2190 C10.1@2676.38,2190 ; J2.1@2665,3332 J2.1@2665,3310.12 2729.88,3310.12 v1(2730,3310) ; C43.1@2920,701.5 2920,760 v1(2900,780) ; C42.1@2920.2,1014.65 2920,1014.45 v1(2920,970) 2920,961.93 U6.25@2956.89,925.04 ; U6.31@2956.89,806.93 2926.93,806.93 v1(2900,780) ; U6.30@2956.89,826.61 2926.61,826.61 2900,800 v1(2900,780) ; v1(3020,2370) R15.2@3068.5,2370 ; v1(3020,2440) R16.2@3068.5,2440 ; U8.15@3033.98,2683.86 3033.98,2723.98 v2(3050,2740) ; R35.2@3040,568.5 3068,568.5 3079.73,580.23 3079.53,580.43 v2(3079.53,700) U6.6@3079.53,762.69 ; U6.6@3079.73,762.69 U6.6@3079.73,762.83 ; U7.10@3095.43,400 v2(3160,400) 3170,400 3190,420 C51.2@3238.5,420 ; U6.16@3143.51,925.04 3143.51,963.51 v1(3160,980) 3160,1024.45 C41.1@3160.2,1024.65 ; R10.1@3150,3001.5 3198.5,3001.5 v2(3200,3000) ; v2(3210,700) C40.1@3258.5,700 ; R41.2@3801.5,720 v2(3850,720) ; R43.2@3801.5,800 v2(3850,800) ; C16.1@1763,2034 1763,1984 C8.1@1763.62,1984 C8.1@1766,1984 ; C16.1@1763,2034 1763,2084 C6.1@1763.62,2084 ; C6.1@1763.62,2084 C6.1@1766,2084 ; C8.1@1766,1984 C6.1@1766,2084
  Solder Side w6: J9.5@669.8,1855 925,1855 980,1800 v1(1290,1800) ; J9.4@769.8,1905 900,2035.2 900,2140 930,2170 v2(950,2170) ; v2(3079.53,700) v2(3210,700)
VCC_5P0: C23.1 C26.1 C50.1 FB1.1 R6.1 R37.2 U2.1 U3.3 | length 2389.6
  Component Side w15: U3.3@1163.35,875 1285,875 1556.38,603.62 C26.1@1770,603.62 1772.33,605.95 U2.1@1929.49,605.95
  Component Side w20: U2.1@1929.49,605.95 1929.49,513.11 R6.1@1926.38,510 1926.38,455.12 C23.1@1930,451.5 1930,230 1963.86,196.14 FB1.1@2758.7,196.14 2758.7,308.7 v1(2770,320) 2738.5,351.5 R37.2@2738.5,390 C50.1@2661.5,390
VCC_ISRC: J3.1 J4.1 R10.2 | length 690.1
  Component Side w6: R10.2@3150,2938.5 3150,2860 3160,2850 J3.1@3229.88,2850 3229.88,2899.88 3260,2930 v2(3590,2930) ; J4.1@3589.88,2825 3589.88,2879.88 v2(3590,2880)
  Solder Side w6: v2(3590,2880) v2(3590,2930)
pads on no net: FID1.1 FID2.1 FID3.1 J3.7 J4.7 J5.1 J5.4 J5.6 J5.8 J5.9 J5.10 J5.11 J6. J6.1 J7.2 J7.3 J7.11 J7.19 J8.1 J8.4 J8.6 J8.9 J8.10 J8.11 J9.7 J9.MH1 J9.MH2 J10.4 U1.18 U1.19 U1.20 U1.21 U1.24 U1.25 U1.35 U1.36 U1.37 U1.38 U1.40 U1.41 U1.60 U1.62 U1.65 U1.67 U1.71 U1.72 U1.73 U1.74 U1.75 U1.76 U1.77 U1.78 U1.102 U1.109 U1.110 U1.111 U1.112 U1.116 U1.117 U1.120 U1.121 U1.123 U1.127 U3.5 U5.1 U6.3 U6.10

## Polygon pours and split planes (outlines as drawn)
E_SHIELD on Ground Plane (split plane): 887.44,2110 887.68,2107.55 888.4,2105.19 889.56,2103.02 891.12,2101.12 893.02,2099.56 895.19,2098.4 897.55,2097.68 900,2097.44 1237.44,2097.44 1237.44,1672.56 900,1672.56 897.55,1672.32 895.19,1671.6 893.02,1670.44 891.12,1668.88 889.56,1666.98 888.4,1664.81 887.68,1662.45 887.44,1660 887.44,1282.56 20.1,1282.56 20.1,2297.44 887.44,2297.44
GND on Ground Plane (split plane): 3879.9,20.1 20.1,20.1 20.1,1257.44 900,1257.44 902.45,1257.68 904.81,1258.4 906.98,1259.56 908.88,1261.12 910.44,1263.02 911.6,1265.19 912.32,1267.55 912.56,1270 912.56,1647.44 1250,1647.44 1252.45,1647.68 1254.81,1648.4 1256.98,1649.56 1258.88,1651.12 1260.44,1653.02 1261.6,1655.19 1262.32,1657.55 1262.56,1660 1262.56,2110 1262.32,2112.45 1261.6,2114.81 1260.44,2116.98 1258.88,2118.88 1256.98,2120.44 1254.81,2121.6 1252.45,2122.32 1250,2122.56 1247.55,2122.32 1245.19,2121.6 1245,2121.5 1244.81,2121.6 1242.45,2122.32 1240,2122.56 912.56,2122.56 912.56,2310 912.32,2312.45 911.6,2314.81 910.44,2316.98 908.88,2318.88 906.98,2320.44 904.81,2321.6 902.45,2322.32 900,2322.56 20.1,2322.56 20.1,3429.9 3879.9,3429.9
VCC_3P3 on Power Plane (split plane): 3879.9,20.1 20.1,20.1 20.1,1264.9 900,1264.9 901.95,1265.29 903.6,1266.4 904.71,1268.05 905.1,1270 905.1,1654.9 1250,1654.9 1251.95,1655.29 1253.6,1656.4 1254.71,1658.05 1255.1,1660 1255.1,2110 1254.71,2111.95 1253.6,2113.6 1251.95,2114.71 1250,2115.1 905.1,2115.1 905.1,2310 904.71,2311.95 903.6,2313.6 901.95,2314.71 900,2315.1 20.1,2315.1 20.1,3429.9 3879.9,3429.9

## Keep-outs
Keep-Out Layer:
  lines w10: -5,0 ccw(c0,0) 0,-5 cw(c0,0) -5,0 ; -5,0 -5,3450 ; -5,3450 cw(c0,3450) 0,3455 ccw(c0,3450) -5,3450 ; 1551.92,-0.51 ccw(c1556.92,-0.51) 1556.92,-5.51 cw(c1556.92,-0.51) 1551.92,-0.51
  text ".Layer_Name" at 577,-858.49 h60

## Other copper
Component Side:
  rectangle net GND: 1890,780 2170,960
  text ".Layer_Name" at 577,-858.49 h60
Solder Side:
  text ".Layer_Name" at 577,-858.49 h60
Ground Plane (plane layer: these items are gaps in the copper):
  lines w10: 1240,2110 1250,2110
  lines w25: 0,1270 900,1270 900,1660 1250,1660 1250,2110 ; 0,2310 900,2310 900,2110 1240,2110
  text ".Layer_Name" at 577,-858.49 h60
Power Plane (plane layer: these items are gaps in the copper):
  rectangle: 900,1660 1250,2110
  rectangle: 0,1270 900,2310
  lines w10: 0,1270 900,1270 900,1660 1250,1660 1250,2110 900,2110 900,2310 0,2310
  text ".Layer_Name" at 577,-858.49 h60

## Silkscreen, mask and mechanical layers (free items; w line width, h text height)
Top Overlay:
  lines w10: 0,1100 1410,1100 ; 280,3450 280,2810 480,2610 1360,2610 1550,2800 1550,3450 ; 1310,2760 1410,2760 ; 1330,2740 1390,2740 ; 1350,2720 1370,2720 ; 1360,2760 1360,2810 ; 1370,800 1470,800 ; 1390,780 1450,780 ; 1400,1100 1410,1100 ; 1410,760 1430,760 ; 1420,800 1420,850 ; 1680,1120 1740,1120 ; 1700,0 1700,810 1410,1100 ; 1720,1100 1740,1120 ; 1720,1140 1740,1120 ; 2999,2040 2979,2060 ; 3000,2080 2980,2060 2979,2060 ; 3050,2060 2979,2060 ; 3580,970 3680,970 ; 3600,950 3660,950 ; 3620,930 3640,930 ; 3630,970 3630,1020 ; 3810,510 3830,530 3830,410 ; 3850,530 3850,410 3870,430
  text "." at 2710,3340 h40
  text "HDR_V" at 2390,2930 h40
  text "JTAG" at 3252.44,2922.44 h40
  text "." at 3210,2920 h40
  text "." at 3530,2880 h40
  text "UART" at 340,2850 h40
  text "Section" at 340,2780 h40
  text "MCU_V" at 2390,2650 h40
  text "JTAG+ETM" at 3860,2460 h40 r90
  text "1.2 V" at 3070,2040 h40
  text "TIDM-TM4C129USBHS" at 2700,1400 h60
  text "A0" at 2700,1320 h60
  text "RESET" at 1240,1220 h40
  text "3.3V" at 1510,1100 h40
  text "CAN Section" at 880,1000 h40
  text "HS" at 3520,670 h40 r270
  text "SW" at 3620,670 h40 r270
  text "FS" at 3720,670 h40 r270
  text ".Layer_Name" at 577,-858.49 h60
Bottom Overlay:
  text "AAA" at 140,220 h40
  text ".Layer_Name" at 577,-858.49 h60
Top Paste:
  text ".Layer_Name" at 577,-858.49 h60
Bottom Paste:
  text ".Layer_Name" at 577,-858.49 h60
Top Solder:
  text ".Layer_Name" at 577,-858.49 h60
  text ".Layer_Name" at 577,-858.49 h60
Bottom Solder:
  text ".Layer_Name" at 577,-858.49 h60
Drill Guide:
  text ".Layer_Name" at 577,-858.49 h60
Mechanical 1:
  lines w10: 2200,0 0,0 ; 2400,0 0,0 ; 0,0 3900,0 ; 0,0 3895,0 3900,0 ; 0,0 0,3450 3900,3450 3900,0
Mechanical 2:
  rectangle: 0,-275 125,-150
  rectangle: 125,-400 500,-275
  rectangle: 125,-400 500,-275
  rectangle: 0,-275 125,-150
  lines w7: 0,-400 1000,-400 ; 0,-400 0,-150 ; 0,-400 0,-150 ; 0,-400 1000,-400 ; 0,-150 1000,-150 ; 0,-150 1000,-150 ; 1000,-400 1000,-150 ; 1000,-400 1000,-150 ; 0,-275 1000,-275 0,-275 ; 125,-400 125,-150 125,-400 ; 250,-400 250,-150 250,-400 ; 500,-400 500,-150 500,-400 ; 750,-400 750,-150 750,-400
  text ".Layer_Name" at 577,-858.49 h60
  text ".Layer_Name" at 577,-858.49 h60
Mechanical 3:
  text ".Layer_Name" at 577,-858.49 h60
  text ".Layer_Name" at 577,-858.49 h60
Mechanical 4:
  text ".Layer_Name" at 577,-858.49 h60
  text ".Layer_Name" at 577,-858.49 h60
Mechanical 5:
  lines w10: 1284,-1133.5 -291.5,-1133.5 ; 2173,-1133.5 2173,-523.5 ; 3440,-726.83 3440,-523.5 ; 4280,-726.83 4280,-523.5 ; 4902,-1140 4902,-937.17 ; -292,-1133.5 -292,-523.5 -292,-1133.5 ; -292,-1133.5 3713,-1133.5 ; -292,-1133.5 3713,-1133.5 ; -291.5,-1133.5 -291.5,-523.5 ; -291.5,-1133.5 -291.5,-523.5 ; -291.5,-523.5 6310,-523.5 ; -291.5,-523.5 6310,-523.5 ; 3713,-1133.5 6310,-1133.5 ; 3713,-1133.5 6310,-1133.5 ; 6310,-1133.5 6310,-523.5 ; 6310,-1133.5 6310,-523.5 ; -292,-930.17 6308,-930.17 -292,-930.17 ; -292,-726.83 6310,-726.83 -292,-726.83
  text "COMPONENTS MARKED 'DNP' SHOULD NOT BE POPULATED." at 1153.5,-318.5 h60
  text "ASSEMBLY VARIANT:" at 1153,-434 h60
  text ".VariantName" at 2189,-434 h60
  text "PCB VIEWED FROM TOP SIDE" at -228.5,-655.67 h60
  text "BOARD #:" at 2248,-655.67 h60
  text ".PRJ_Number" at 2793.5,-655.67 h60
  text "REV:" at 3638,-655.67 h60
  text ".PCB_Rev" at 3929.5,-655.67 h60
  text "SVN REV:" at 4476,-655.67 h60
  text ".VersionControl_RevNumber" at 4982,-655.67 h60
  text "LAYER NAME =" at -228.5,-858.49 h60
  text "TID #:" at 2248,-859 h60
  text ".TID" at 2793.5,-859 h60
  text "PLOT NAME =" at -228.5,-1064.34 h60
  text ".plot_File_Name" at 577,-1064.34 h60
  text "GENERATED    :" at 2250,-1064.34 h60
  text ".Print_Date" at 3119.5,-1064.34 h60
  text ".Print_Time" at 3848.5,-1064.34 h60
  text "TEXAS INSTRUMENTS" at 5113,-1064.34 h60
Mechanical 6:
  lines w10: 1115.5,-1140.5 1115.5,-937.67 ; 1737.5,-727.33 1737.5,-524 ; 2577.5,-727.33 2577.5,-524 ; 3844.5,-1134 3844.5,-524 ; -292.5,-1134 -292.5,-524 ; -292.5,-1134 2304.5,-1134 ; -292.5,-1134 2304.5,-1134 ; -292.5,-1134 -292.5,-524 ; -292.5,-524 6309,-524 ; -292.5,-524 6309,-524 ; 2304.5,-1134 6309.5,-1134 ; 2304.5,-1134 6309.5,-1134 ; 6309,-1134 6309,-524 ; 6309,-1134 4733.5,-1134 6309,-1134 ; 6309,-1134 6309,-524 ; 6309.5,-1134 6309.5,-524 6309.5,-1134 ; -292.5,-727.33 6309.5,-727.33 -292.5,-727.33 ; -290.5,-930.67 6309.5,-930.67 -290.5,-930.67
  text "COMPONENTS MARKED 'DNP' SHOULD NOT BE POPULATED." at 6102,-318 h60
  text ".VariantName" at 5058,-434 h60
  text "ASSEMBLY VARIANT:" at 6097,-434 h60
  text ".VersionControl_RevNumber" at 1035.5,-656.17 h60
  text "SVN REV:" at 1541.5,-656.17 h60
  text ".PCB_Rev" at 2088,-656.17 h60
  text "REV:" at 2379.5,-656.17 h60
  text ".PRJ_Number" at 3224,-656.17 h60
  text "BOARD #:" at 3769.5,-656.17 h60
  text "PCB VIEWED FROM BOTTOM SIDE" at 6246,-656.17 h60
  text ".TID" at 3224,-859.5 h60
  text "TID #:" at 3769.5,-859.5 h60
  text "TEXAS INSTRUMENTS" at 904.5,-1064.84 h60
  text ".Print_Time" at 2169,-1064.84 h60
  text ".Print_Date" at 2898,-1064.84 h60
  text "GENERATED    :" at 3767.5,-1064.84 h60
  text ".plot_File_Name" at 5440.5,-1064.84 h60
  text "PLOT NAME =" at 6246,-1064.84 h60
Mechanical 9:
  drawing of 56 lines, arcs and shapes, not listed
  text "1" at 739.84,8036.5 h70
  text "2" at 3235.5,8036.5 h70
  text "3" at 5724.84,8036.5 h70
  text "4" at 8231.51,8036.5 h70
  text "5" at 10730.5,8036.5 h70
  text "A" at -416.5,6893.5 h70
  text "B" at -416.5,4513.5 h70
  text "6" at 10180.5,4436.5 h70
  text "A" at 11328.5,3293.5 h70
  text "C" at -416.5,2138.5 h70
  text "C" at 14383.5,2138.5 h70
  text "B" at 11328.5,913.5 h70
  text "PROJECT TITLE:" at 11343.5,277.5 h45
  text ".PRJ_Title" at 11393.5,144.17 h70
  text "DESIGNED FOR:" at 11343.5,-23.5 h45
  text ".PRJ_Customer" at 11393.5,-163.5 h70
  text "D" at -416.5,-231.5 h70
  text "D" at 14383.5,-231.5 h70
  text "FILE NAME:" at 11343.5,-323.5 h45
  text ".PCB_File_Name_No_Path" at 11393.5,-443.5 h70
  text "Texas Instruments (TI) and/or its licensors do not warrant the accuracy or completeness of this specification" at 6374,-605.34 h45
  text "ENGINEER:" at 11343.5,-613.5 h45
  text "LAYOUT BY:" at 12848.5,-613.5 h45
  text "or any information contained therein. TI and/or its licensors do not warrant that this design will meet" at 6329.01,-718 h45
  text ".PRJ_Engineer" at 11393.5,-768.49 h70
  text ".PCB_Layout" at 12899,-768.49 h70
  text "the specifications, will be suitable for your application or fit for any particular purpose, or will operate in" at 6329.01,-830.67 h45
  text "ALTIUM DESIGNER VERSION:" at 12848.5,-923.5 h45
  text "an implementation. TI and/or its licensors do not warrant that the design is production worthy. You should" at 6329.01,-943.33 h45
  text "completely validate and test your design implementation to confirm the system functionality for your application." at 6374,-1056 h45
  text ".print_Scale" at 11393.5,-1056.83 h70
  text ".Application_BuildNumber" at 12899,-1056.83 h70
  text "1" at 739.84,-1263.5 h70
  text "2" at 3235.5,-1263.5 h70
  text "3" at 5724.84,-1263.5 h70
  text "4" at 8231.51,-1263.5 h70
  text "5" at 10730.5,-1263.5 h70
  text "6" at 13235.5,-1263.5 h70
Mechanical 10:
  drawing of 173 lines, arcs and shapes, not listed
  text "DESIGN INFORMATION" at 12377.02,6201 h60
  text "MIN. TRACK WIDTH:" at 11732.46,6021 h60
  text "8" at 12828.7,6021 h60
  text "MIL" at 12983.46,6021 h60
  text "MIN. CLEARANCE:" at 11732.46,5889 h60
  text "0.2" at 12768.7,5889 h60
  text "mm" at 12983.46,5889 h60
  text "MIN. VIA PAD SIZE:" at 11732.46,5757 h60
  text "24" at 12798.71,5757 h60
  text "MIL" at 12983.46,5757 h60
  text "0.05mm (2MIL)" at 12427.46,5615.29 h60
  text "MINIMUM ANNULAR RING" at 11403.23,5611 h60
  text "EXTERNAL" at 13135.46,5611 h60
  text "PER" at 11603.23,5493 h60
  text "IPC-D-275 CLASS 2 LEVEL C" at 11823.23,5493 h60
  text "MIL, HOLES" at 13311.46,5380.71 h60
  text "+/-" at 12919,5380 h60
  text "+/-" at 13773,5380 h60
  text "REGISTRATION TOLERANCES:" at 11403.23,5375 h60
  text "METAL" at 12603,5375 h60
  text "5" at 13179.2,5375 h60
  text "3" at 14012.2,5375 h60
  text "MIL" at 14128.46,5375 h60
  text "+/-" at 13773,5262 h60
  text "HOLE SIZE TOLERANCE (UNLESS OTHERWISE SPECIFIED):" at 11403.23,5257 h60
  text "3" at 14012.2,5257 h60
  text "MIL" at 14128.46,5257 h60
  text "MATERIAL:" at 11328.46,5047.54 h60
  text "FR-4 High Tg" at 12314.9,4907.21 h60
  text "FR-408" at 11749.46,4898.64 h60
  text "OTHER" at 13237.46,4898.64 h60
  text "X" at 12160,4895 h60
  text "62 MIL (1.6mm) +/-10%" at 12069.56,4735.92 h60
  text "THICKNESS:" at 11403.23,4731.64 h60
  text "X" at 11941.4,4731.64 h60
  text "OTHER" at 13354.46,4731.64 h60
  text "TOLERANCE:" at 11403.23,4573.64 h60
  text "X" at 12242.53,4573.64 h60
  text "ANSI IPC-6012 TYPE 3 CLASS 2" at 12429.48,4573.64 h60
  text "OTHER +/-" at 12429.46,4417.64 h60
  text "BOW & TWIST:" at 11403.23,4260.64 h60
  text "X" at 12242.53,4260.64 h60
  text "ANSI IPC-6012 TYPE 3 CLASS 2" at 12429.48,4260.64 h60
  text "OTHER +/-" at 12429.46,4102.13 h60
  text "DRILLING:" at 11328.46,3963.64 h60
  text "REFERENCE:" at 11403.23,3846.64 h60
  text "X" at 12051.46,3846.64 h60
  text "AS SHOWN" at 12238.46,3846.64 h60
  text "X" at 12952.46,3846.64 h60
  text "NC_DRILL FILES" at 13089.46,3846.64 h60
  text "PTH MIN COPPER THICKNESS:" at 11403.23,3688.64 h60
  text "X" at 12753.46,3688.64 h60
  text "1MIL" at 12890.46,3688.64 h60
  text "OTHER" at 13387.46,3688.64 h60
  text "BOARD FINISH:" at 11328.46,3529.64 h60
  text "SILKSCREEN:" at 11483.68,3411.64 h60
  text "X" at 12432.46,3411.64 h60
  text "TOP" at 12558.46,3411.64 h60
  text "X" at 12942.46,3411.64 h60
  text "BOTTOM" at 13069.46,3411.64 h60
  text "SILKSCREEN COLOR:" at 11483.68,3244.64 h60
  text "X" at 12431.42,3244.64 h60
  text "WHITE" at 12558.46,3244.64 h60
  text "OTHER" at 13069.46,3244.64 h60
  text "X" at 12562.42,3085.44 h60
  text "GREEN" at 12689.46,3085.44 h60
  text "OTHER" at 13307.46,3085.44 h60
  text "SOLDER RESIST COLOR:" at 11483.68,3074.64 h60
  text "X" at 12562.42,2915.44 h60
  text "MATTE" at 12689.46,2915.44 h60
  text "SEMI-GLOSS" at 13307,2914.8 h60
  text "IMMERSION GOLD (ENIG)" at 12389.46,2726.92 h60
  text "ENEPIG" at 13727,2723.64 h60
  text "SURFACE FINISH:" at 11328.46,2722.64 h60
  text "X" at 12202.51,2722.64 h60
  text "IMM. TIN/SILVER OR EQUIV" at 11658,2565.64 h60
  text "OTHER" at 13089.46,2565.64 h60
  text "ARRAY/PANEL:" at 11328.46,2386.64 h60
  text "CUT AND TRIM PER M1 BOARD OUTLINE" at 12389.46,2382.35 h60
  text "N.C. ROUTE" at 12389.46,2230.64 h60
  text "X" at 13068.46,2230.64 h60
  text "V. SCORE" at 13255.46,2230.64 h60
  text "CERTIFICATION:" at 11328.46,2093.64 h60
  text "MATERIALS AND WORKMANSHIP FOR ALL PCBS" at 12053.46,2093.64 h60
  text "TO MEET OR EXCEED THE REQUIREMENTS OF:" at 12053.46,1995.64 h60
  text "X" at 11679.96,1859.13 h60
  text "ANSI IPC-A-600F CLASS ->" at 11818.96,1859.13 h60
  text "X" at 13458.02,1859.13 h60
  text "2" at 13576.96,1859.14 h60
  text "1" at 13261.96,1857.64 h60
  text "3" at 13930.96,1857.64 h60
  text "X" at 12494.02,1699.64 h60
  text "RoHS" at 12630.96,1699.64 h60
  text "OTHER" at 13275.36,1699.64 h60
  text "PER ORDER" at 13672.42,1699.64 h60
  text "ALL BOARDS MUST MEET OR EXCEED UL94-V0 REQUIREMENTS." at 11356,1534 h60
  text "PCB MUST BEAR THE UL94V-0 UL REGISTERED MATERIAL ID NUMBER" at 11356,1414 h60
  text "ADDITIONAL REQUIREMENTS:" at 11328.46,1240.64 h60
  text "MICROSECTION:" at 11403.23,1125.64 h60
  text "YES" at 12308.96,1125.64 h60
  text "REQUIRED" at 13170.46,969.49 h60
  text "BARE BOARD ELEC. TEST:" at 11403.23,966.64 h60
  text "NONE" at 12708.96,966.64 h60
  text "X" at 13043.46,966.64 h60
  text "PER ORDER" at 13762.46,966.64 h60
  text ".Layer_Name" at 577,-858.49 h60
  text ".Layer_Name" at 577,-858.49 h60
Mechanical 11:
  lines w10: 1284,-1133.5 -291.5,-1133.5 ; 2173,-1133.5 2173,-523.5 ; 3440,-726.83 3440,-523.5 ; 4280,-726.83 4280,-523.5 ; 4902,-1140 4902,-937.17 ; -292,-1133.5 3713,-1133.5 ; -292,-1133.5 -292,-523.5 -292,-1133.5 ; -292,-1133.5 3713,-1133.5 ; -291.5,-1133.5 -291.5,-523.5 ; -291.5,-1133.5 -291.5,-523.5 ; -291.5,-523.5 6310,-523.5 ; -291.5,-523.5 6310,-523.5 ; 3713,-1133.5 6310,-1133.5 ; 3713,-1133.5 6310,-1133.5 ; 6310,-1133.5 6310,-523.5 ; 6310,-1133.5 6310,-523.5 ; -292,-930.17 6308,-930.17 -292,-930.17 ; -292,-726.83 6310,-726.83 -292,-726.83
  text "ALL ARTWORK VIEWED FROM TOP SIDE" at -228.5,-655.67 h60
  text "BOARD #:" at 2248,-655.67 h60
  text ".PRJ_Number" at 2793.5,-655.67 h60
  text "REV:" at 3638,-655.67 h60
  text ".PCB_Rev" at 3929.5,-655.67 h60
  text "SVN REV:" at 4476,-655.67 h60
  text ".VersionControl_RevNumber" at 4982,-655.67 h60
  text "LAYER NAME =" at -228.5,-858.49 h60
  text "TID #:" at 2248,-859 h60
  text ".TID" at 2793.5,-859 h60
  text "PLOT NAME =" at -228.5,-1064.34 h60
  text ".plot_File_Name" at 577,-1064.34 h60
  text "GENERATED    :" at 2250,-1064.34 h60
  text ".Print_Date" at 3119.5,-1064.34 h60
  text ".Print_Time" at 3848.5,-1064.34 h60
  text "TEXAS INSTRUMENTS" at 5113,-1064.34 h60
Mechanical 12:
  drawing of 295 lines, arcs and shapes, not listed
  text "Layer" at 9790.58,7830 h60
  text "Name" at 10200.49,7830 h60
  text "Material" at 11140.23,7830 h60
  text "Thickness" at 12000,7830 h60
  text "Constant" at 12649.83,7830 h60
  text "Board Layer Stack" at 13219.69,7830 h60
  text "1" at 9790.58,7710 h60
  text "Top Overlay" at 10200.49,7710 h60
  text "2" at 9790.58,7590 h60
  text "Top Solder" at 10200.49,7590 h60
  text "Solder Resist" at 11140.23,7590 h60
  text "0.40mil" at 12000,7590 h60
  text "3.5" at 12649.83,7590 h60
  text "3" at 9790.58,7470 h60
  text "Component Side" at 10200.49,7470 h60
  text "Copper" at 11140.23,7470 h60
  text "1.40mil" at 12000,7470 h60
  text "4" at 9790.58,7350 h60
  text "Dielectric 1" at 10200.49,7350 h60
  text "FR-4" at 11140.23,7350 h60
  text "13.00mil" at 12000,7350 h60
  text "4.8" at 12649.83,7350 h60
  text "5" at 9790.58,7230 h60
  text "Ground Plane" at 10200.49,7230 h60
  text "Copper" at 11140.23,7230 h60
  text "1.40mil" at 12000,7230 h60
  text "6" at 9790.58,7110 h60
  text "Dielectric 3" at 10200.49,7110 h60
  text "28.00mil" at 12000,7110 h60
  text "4.2" at 12649.83,7110 h60
  text "7" at 9790.58,6990 h60
  text "Power Plane" at 10200.49,6990 h60
  text "Copper" at 11140.23,6990 h60
  text "1.40mil" at 12000,6990 h60
  text "8" at 9790.58,6870 h60
  text "Dielectric 4" at 10200.49,6870 h60
  text "13.00mil" at 12000,6870 h60
  text "4.2" at 12649.83,6870 h60
  text "9" at 9790.58,6750 h60
  text "Solder Side" at 10200.49,6750 h60
  text "Copper" at 11140.23,6750 h60
  text "1.40mil" at 12000,6750 h60
  text "10" at 9790.58,6630 h60
  text "Bottom Solder" at 10200.49,6630 h60
  text "Solder Resist" at 11140.23,6630 h60
  text "0.40mil" at 12000,6630 h60
  text "3.5" at 12649.83,6630 h60
  text "11" at 9790.58,6510 h60
  text "Bottom Overlay" at 10200.49,6510 h60
  text ".Layer_Name" at 577,-858.49 h60
  text ".Layer_Name" at 577,-858.49 h60
Mechanical 13:
  text ".Layer_Name" at 577,-858.49 h60
  text ".Layer_Name" at 577,-858.49 h60
Mechanical 14:
  text ".Layer_Name" at 577,-858.49 h60
  text ".Layer_Name" at 577,-858.49 h60
Mechanical 15:
  text ".Layer_Name" at 577,-858.49 h60
  text ".Layer_Name" at 577,-858.49 h60
Mechanical 16:
  text ".Layer_Name" at 577,-858.49 h60
  text ".Layer_Name" at 577,-858.49 h60
Drill Drawing:
  text ".Layer_Name" at 577,-858.49 h60

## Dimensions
0,-400 to 1000,-400 on Mechanical 2
0,0 to 0,3450 on Mechanical 2
0,0 to 3900,0 on Mechanical 2
0,-400 to 1000,-400 on Mechanical 2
